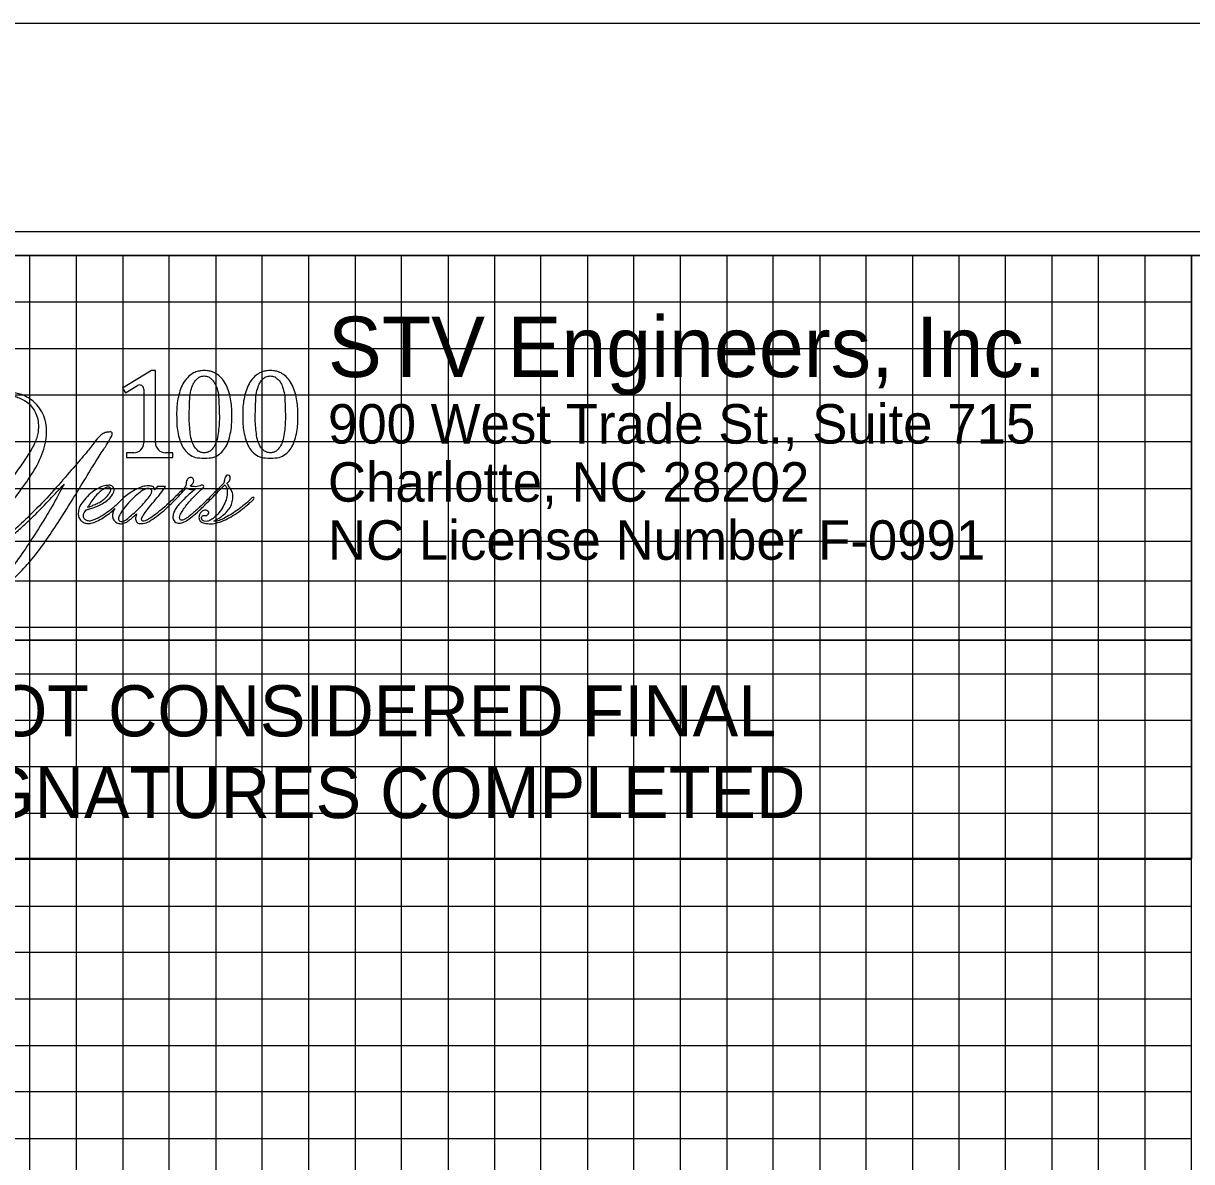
# Model space of a CAD drawing. Extents: x 3814791 to 3815465, y 1224203 to 1224643.
# Drawn here: x 3815327.8 to 3815378.1, y 1224594.2 to 1224643.2 of the extents above; entities that cross this region are included whole.
import ezdxf

# ---------------------------------------------------------------- set-up
doc = ezdxf.new("R2010")
doc.units = 0
for name, color, linetype in [('COGO Default Curve', 7, 'Continuous'), ('Exist Roads EOP', 7, 'Continuous'), ('Pattern 49', 7, 'Continuous'), ('Scratch_Level_1', 7, 'Continuous'), ('Sheet Layout Plan Border', 7, 'Continuous'), ('UC Full Profile Sheet 34 CELL', 7, 'Continuous')]:
    doc.layers.add(name, color=color, linetype=linetype)

msp = doc.modelspace()

# ---------------------------------------------------------------- linework, layer by layer
at = {"layer": 'COGO Default Curve'}
for p, q in [((3815298.107, 1224616.652), (3815378.107, 1224616.652)), ((3815378.107, 1224616.652), (3815378.107, 1224607.252)), ((3815378.107, 1224607.252), (3815298.107, 1224607.252))]:
    msp.add_line(p, q, dxfattribs=at)
at = {"layer": 'Exist Roads EOP'}
for p, q in [((3814878.107, 1224633.207), (3815378.107, 1224633.207)), ((3815378.107, 1224623.187), (3815378.132, 1224633.207))]:
    msp.add_line(p, q, dxfattribs=at)
for points in [[(3815458.107, 1224633.207), (3814858.107, 1224633.207), (3814858.107, 1224213.207), (3815458.107, 1224213.207)], [(3814878.107, 1224633.207), (3814878.107, 1224223.207), (3815438.107, 1224223.207), (3815438.107, 1224578.187), (3815378.107, 1224578.187), (3815378.107, 1224633.207)]]:
    msp.add_lwpolyline(points, close=True, dxfattribs=at)
for points in [[(3815328.107, 1224223.207), (3815328.107, 1224633.207), (3815348.107, 1224633.207), (3815348.107, 1224223.207)], [(3815330.107, 1224223.207), (3815330.107, 1224633.207), (3815332.107, 1224633.207), (3815332.107, 1224223.207)], [(3815334.107, 1224223.207), (3815334.107, 1224633.207), (3815336.107, 1224633.207), (3815336.107, 1224223.207)], [(3815338.107, 1224223.207), (3815338.107, 1224633.207), (3815358.107, 1224633.207), (3815358.107, 1224223.207)], [(3815340.107, 1224223.207), (3815340.107, 1224633.207), (3815342.107, 1224633.207), (3815342.107, 1224223.207)], [(3815344.107, 1224223.207), (3815344.107, 1224633.207), (3815346.107, 1224633.207), (3815346.107, 1224223.207)], [(3815350.107, 1224223.207), (3815350.107, 1224633.207), (3815352.107, 1224633.207), (3815352.107, 1224223.207)], [(3815354.107, 1224223.207), (3815354.107, 1224633.207), (3815356.107, 1224633.207), (3815356.107, 1224223.207)], [(3815360.107, 1224223.207), (3815360.107, 1224633.207), (3815362.107, 1224633.207), (3815362.107, 1224223.207)], [(3815364.107, 1224223.207), (3815364.107, 1224633.207), (3815366.107, 1224633.207), (3815366.107, 1224223.207)], [(3815368.107, 1224223.207), (3815368.107, 1224633.207)], [(3815370.107, 1224223.207), (3815370.107, 1224633.207), (3815372.107, 1224633.207), (3815372.107, 1224223.207)], [(3815374.107, 1224223.207), (3815374.107, 1224633.207), (3815376.107, 1224633.207), (3815376.107, 1224223.207)], [(3815378.107, 1224223.207), (3815378.107, 1224633.207), (3815388.627, 1224633.207)], [(3815418.137, 1224623.252), (3815418.137, 1224578.187), (3815378.107, 1224578.187), (3815378.107, 1224633.207), (3815418.137, 1224633.207), (3815418.137, 1224633.147)], [(3815378.087, 1224631.207), (3814878.107, 1224631.207), (3814878.107, 1224629.207), (3815378.087, 1224629.207)], [(3815378.087, 1224627.207), (3814878.107, 1224627.207), (3814878.107, 1224625.207), (3815378.087, 1224625.207)], [(3815378.087, 1224603.207), (3814858.147, 1224603.207), (3814858.147, 1224623.187), (3815378.087, 1224623.187)], [(3815378.087, 1224620.907), (3814878.107, 1224620.907), (3814878.107, 1224619.207), (3815378.087, 1224619.207)], [(3815378.087, 1224617.207), (3814878.107, 1224617.207), (3814878.107, 1224615.207), (3815378.087, 1224615.207)], [(3814858.107, 1224613.207), (3815378.087, 1224613.207)], [(3815378.087, 1224611.207), (3814878.107, 1224611.207), (3814878.107, 1224609.207), (3815378.087, 1224609.207)], [(3815378.107, 1224607.207), (3814878.107, 1224607.207), (3814878.107, 1224605.207), (3815378.087, 1224605.207)], [(3815378.087, 1224601.207), (3814878.107, 1224601.207), (3814878.107, 1224599.207), (3815378.087, 1224599.207)], [(3815378.087, 1224597.207), (3814878.107, 1224597.207), (3814878.107, 1224595.207), (3815378.087, 1224595.207)]]:
    msp.add_lwpolyline(points, dxfattribs=at)
at = {"layer": 'Pattern 49'}
msp.add_lwpolyline([(3815463.107, 1224634.227), (3814796.507, 1224634.227), (3814796.507, 1224212.187), (3815463.107, 1224212.187)], close=True, dxfattribs=at)
at = {"layer": 'Scratch_Level_1'}
msp.add_lwpolyline([(3815464.907, 1224643.207), (3814791.307, 1224643.207), (3814791.307, 1224203.207), (3815464.907, 1224203.207)], close=True, dxfattribs=at)
at = {"layer": 'Sheet Layout Plan Border'}
for p, q in [((3815333.337, 1224628.261), (3815332.095, 1224627.499)), ((3815333.51, 1224628.261), (3815333.337, 1224628.261)), ((3815333.51, 1224625.153), (3815333.51, 1224628.261)), ((3815332.222, 1224627.301), (3815332.737, 1224627.617)), ((3815332.095, 1224627.499), (3815332.222, 1224627.301)), ((3815333.008, 1224627.465), (3815333.008, 1224625.153)), ((3815332.581, 1224624.726), (3815332.261, 1224624.726)), ((3815332.261, 1224624.726), (3815332.261, 1224624.517)), ((3815334.258, 1224624.726), (3815333.938, 1224624.726)), ((3815334.258, 1224624.517), (3815334.258, 1224624.726)), ((3815335.613, 1224624.718), (3815335.61, 1224624.718)), ((3815338.456, 1224624.718), (3815338.454, 1224624.718)), ((3815332.261, 1224624.517), (3815334.258, 1224624.517)), ((3815335.611, 1224624.489), (3815335.612, 1224624.489)), ((3815338.455, 1224624.489), (3815338.455, 1224624.489))]:
    msp.add_line(p, q, dxfattribs=at)
msp.add_lwpolyline([(3815298.107, 1224633.207), (3815378.107, 1224633.207), (3815378.107, 1224616.652), (3815298.107, 1224616.652)], close=True, dxfattribs=at)
for centre, radius, start, end in [((3815332.83, 1224627.465), 0.178, 360, 121.5268), ((3815332.581, 1224625.153), 0.428, 270, 0), ((3815333.938, 1224625.153), 0.428, 180, 270)]:
    msp.add_arc(centre, radius, start, end, dxfattribs=at)
for points, degree in [([(3815335.611, 1224628.261), (3815335.58, 1224628.26), (3815335.478, 1224628.257), (3815335.31, 1224628.228), (3815335.097, 1224628.14), (3815334.88, 1224627.971), (3815334.681, 1224627.703), (3815334.561, 1224627.388), (3815334.47, 1224627.04), (3815334.43, 1224626.713), (3815334.423, 1224626.482), (3815334.421, 1224626.389)], 3), ([(3815336.802, 1224626.389), (3815336.799, 1224626.482), (3815336.793, 1224626.713), (3815336.753, 1224627.04), (3815336.662, 1224627.388), (3815336.541, 1224627.703), (3815336.342, 1224627.971), (3815336.126, 1224628.14), (3815335.913, 1224628.228), (3815335.745, 1224628.257), (3815335.643, 1224628.26), (3815335.611, 1224628.261)], 3), ([(3815338.455, 1224628.261), (3815338.424, 1224628.26), (3815338.321, 1224628.257), (3815338.154, 1224628.228), (3815337.94, 1224628.14), (3815337.724, 1224627.971), (3815337.525, 1224627.703), (3815337.405, 1224627.388), (3815337.314, 1224627.04), (3815337.274, 1224626.713), (3815337.267, 1224626.482), (3815337.265, 1224626.389)], 3), ([(3815339.646, 1224626.389), (3815339.643, 1224626.482), (3815339.636, 1224626.713), (3815339.597, 1224627.04), (3815339.505, 1224627.388), (3815339.385, 1224627.703), (3815339.186, 1224627.971), (3815338.97, 1224628.14), (3815338.756, 1224628.228), (3815338.589, 1224628.257), (3815338.486, 1224628.26), (3815338.455, 1224628.261)], 3), ([(3815334.964, 1224626.389), (3815334.968, 1224626.538), (3815334.977, 1224626.832), (3815334.991, 1224627.239), (3815335.078, 1224627.566), (3815335.193, 1224627.785), (3815335.31, 1224627.917), (3815335.425, 1224627.992), (3815335.513, 1224628.02), (3815335.575, 1224628.024), (3815335.611, 1224628.027)], 3), ([(3815335.611, 1224628.027), (3815335.648, 1224628.024), (3815335.71, 1224628.02), (3815335.798, 1224627.992), (3815335.913, 1224627.917), (3815336.03, 1224627.785), (3815336.145, 1224627.566), (3815336.232, 1224627.239), (3815336.246, 1224626.832), (3815336.254, 1224626.538), (3815336.259, 1224626.389)], 3), ([(3815337.808, 1224626.389), (3815337.812, 1224626.538), (3815337.821, 1224626.832), (3815337.835, 1224627.239), (3815337.922, 1224627.566), (3815338.036, 1224627.785), (3815338.153, 1224627.917), (3815338.269, 1224627.992), (3815338.357, 1224628.02), (3815338.419, 1224628.024), (3815338.455, 1224628.027)], 3), ([(3815338.455, 1224628.027), (3815338.491, 1224628.024), (3815338.553, 1224628.02), (3815338.641, 1224627.992), (3815338.757, 1224627.917), (3815338.874, 1224627.785), (3815338.989, 1224627.566), (3815339.075, 1224627.239), (3815339.09, 1224626.832), (3815339.098, 1224626.538), (3815339.102, 1224626.389)], 3), ([(3815329.579, 1224623.37), (3815329.48, 1224623.182), (3815329.145, 1224622.541), (3815328.559, 1224621.583), (3815327.905, 1224620.564), (3815327.301, 1224619.72), (3815326.755, 1224619.129), (3815326.278, 1224618.692), (3815325.912, 1224618.471), (3815325.578, 1224618.312), (3815325.273, 1224618.284), (3815325.005, 1224618.326), (3815324.819, 1224618.475), (3815324.729, 1224618.652), (3815324.739, 1224618.8), (3815324.823, 1224618.892), (3815324.952, 1224618.897), (3815325.113, 1224618.904), (3815325.316, 1224618.974), (3815325.376, 1224619.217), (3815325.208, 1224619.41), (3815324.944, 1224619.393), (3815324.741, 1224619.217), (3815324.57, 1224618.983), (3815324.588, 1224618.694), (3815324.672, 1224618.439), (3815324.863, 1224618.251), (3815325.148, 1224618.157), (3815325.447, 1224618.169), (3815325.782, 1224618.232), (3815326.176, 1224618.393), (3815326.609, 1224618.663), (3815327.118, 1224619.03), (3815327.702, 1224619.583), (3815328.276, 1224620.224), (3815328.842, 1224620.996), (3815329.371, 1224621.797), (3815330.015, 1224622.822), (3815330.587, 1224623.772), (3815331.072, 1224624.563), (3815331.375, 1224625.002), (3815331.546, 1224625.309), (3815331.648, 1224625.457), (3815331.669, 1224625.635), (3815331.494, 1224625.613), (3815331.348, 1224625.603), (3815331.179, 1224625.505), (3815330.995, 1224625.331), (3815330.752, 1224624.985), (3815330.309, 1224624.456), (3815329.642, 1224623.687), (3815328.836, 1224622.757), (3815327.977, 1224621.898), (3815327.33, 1224621.296), (3815326.897, 1224621.026), (3815326.704, 1224620.914), (3815326.492, 1224620.904), (3815326.428, 1224621.1), (3815326.477, 1224621.314), (3815326.661, 1224621.749), (3815326.984, 1224622.165), (3815327.421, 1224622.729), (3815327.888, 1224623.348), (3815328.443, 1224624.171), (3815328.82, 1224625.107), (3815328.854, 1224626.058), (3815328.487, 1224626.765), (3815327.968, 1224627.164), (3815327.513, 1224627.304), (3815327.23, 1224627.348), (3815327.124, 1224627.359)], 3), ([(3815327.277, 1224627.183), (3815327.281, 1224627.182), (3815327.347, 1224627.169), (3815327.47, 1224627.146), (3815327.702, 1224627.074), (3815327.938, 1224626.939), (3815328.175, 1224626.739), (3815328.324, 1224626.502), (3815328.443, 1224626.242), (3815328.481, 1224625.926), (3815328.461, 1224625.507), (3815328.279, 1224625.035), (3815327.959, 1224624.515), (3815327.58, 1224623.964), (3815327.008, 1224623.21), (3815326.426, 1224622.443), (3815326.116, 1224621.654), (3815326.097, 1224621.181), (3815326.2, 1224620.905), (3815326.385, 1224620.765), (3815326.559, 1224620.758), (3815326.796, 1224620.797), (3815327.062, 1224620.953), (3815327.382, 1224621.175), (3815327.809, 1224621.568), (3815328.345, 1224622.056), (3815328.964, 1224622.718), (3815329.362, 1224623.14), (3815329.579, 1224623.37)], 3), ([(3815334.421, 1224626.389), (3815334.423, 1224626.313), (3815334.43, 1224626.114), (3815334.434, 1224625.794), (3815334.504, 1224625.445), (3815334.6, 1224625.113), (3815334.756, 1224624.846), (3815334.947, 1224624.65), (3815335.225, 1224624.499), (3815335.458, 1224624.493), (3815335.611, 1224624.489)], 3), ([(3815335.61, 1224624.718), (3815335.559, 1224624.722), (3815335.437, 1224624.732), (3815335.272, 1224624.854), (3815335.128, 1224625.072), (3815335.027, 1224625.369), (3815334.993, 1224625.723), (3815334.958, 1224626.064), (3815334.962, 1224626.287), (3815334.964, 1224626.389)], 3), ([(3815335.612, 1224624.489), (3815335.765, 1224624.493), (3815335.998, 1224624.499), (3815336.276, 1224624.65), (3815336.467, 1224624.846), (3815336.622, 1224625.113), (3815336.718, 1224625.445), (3815336.789, 1224625.794), (3815336.793, 1224626.114), (3815336.799, 1224626.313), (3815336.802, 1224626.389)], 3), ([(3815336.259, 1224626.389), (3815336.261, 1224626.287), (3815336.265, 1224626.064), (3815336.23, 1224625.723), (3815336.196, 1224625.369), (3815336.094, 1224625.072), (3815335.951, 1224624.854), (3815335.786, 1224624.732), (3815335.664, 1224624.722), (3815335.613, 1224624.718)], 3), ([(3815337.265, 1224626.389), (3815337.267, 1224626.313), (3815337.274, 1224626.114), (3815337.277, 1224625.794), (3815337.348, 1224625.445), (3815337.444, 1224625.113), (3815337.6, 1224624.846), (3815337.791, 1224624.65), (3815338.069, 1224624.499), (3815338.301, 1224624.493), (3815338.455, 1224624.489)], 3), ([(3815338.454, 1224624.718), (3815338.403, 1224624.722), (3815338.281, 1224624.732), (3815338.115, 1224624.854), (3815337.972, 1224625.072), (3815337.87, 1224625.369), (3815337.837, 1224625.723), (3815337.802, 1224626.064), (3815337.806, 1224626.287), (3815337.808, 1224626.389)], 3), ([(3815338.455, 1224624.489), (3815338.609, 1224624.493), (3815338.842, 1224624.499), (3815339.119, 1224624.65), (3815339.31, 1224624.846), (3815339.466, 1224625.113), (3815339.562, 1224625.445), (3815339.633, 1224625.794), (3815339.636, 1224626.114), (3815339.643, 1224626.313), (3815339.646, 1224626.389)], 3), ([(3815339.102, 1224626.389), (3815339.104, 1224626.287), (3815339.108, 1224626.064), (3815339.074, 1224625.723), (3815339.04, 1224625.369), (3815338.938, 1224625.072), (3815338.795, 1224624.854), (3815338.629, 1224624.732), (3815338.508, 1224624.722), (3815338.456, 1224624.718)], 3), ([(3815336.019, 1224621.775), (3815336.06, 1224621.797), (3815336.194, 1224621.867), (3815336.403, 1224622.012), (3815336.61, 1224622.199), (3815336.765, 1224622.425), (3815336.845, 1224622.676), (3815336.854, 1224622.946), (3815336.771, 1224623.146), (3815336.671, 1224623.263), (3815336.635, 1224623.342), (3815336.592, 1224623.387), (3815336.608, 1224623.448), (3815336.675, 1224623.472), (3815336.718, 1224623.556), (3815336.742, 1224623.646), (3815336.707, 1224623.76), (3815336.587, 1224623.77), (3815336.516, 1224623.686), (3815336.464, 1224623.581), (3815336.491, 1224623.428), (3815336.326, 1224623.304), (3815336.156, 1224623.103), (3815335.85, 1224622.807), (3815335.545, 1224622.496), (3815335.265, 1224622.259), (3815335.104, 1224622.103), (3815334.969, 1224621.986), (3815334.827, 1224621.894), (3815334.717, 1224621.823), (3815334.576, 1224621.801), (3815334.538, 1224621.936), (3815334.57, 1224622.041), (3815334.653, 1224622.193), (3815334.776, 1224622.379), (3815334.944, 1224622.599), (3815335.114, 1224622.78), (3815335.287, 1224622.949), (3815335.431, 1224623.106), (3815335.557, 1224623.191), (3815335.612, 1224623.271), (3815335.543, 1224623.356), (3815335.429, 1224623.3), (3815335.306, 1224623.256), (3815335.194, 1224623.267), (3815334.981, 1224623.267), (3815335.043, 1224623.326), (3815335.081, 1224623.367), (3815335.168, 1224623.438), (3815335.167, 1224623.582), (3815335.069, 1224623.677), (3815334.948, 1224623.654), (3815334.869, 1224623.563), (3815334.822, 1224623.454), (3815334.84, 1224623.365), (3815334.79, 1224623.235), (3815334.627, 1224623.094), (3815334.384, 1224622.842), (3815334.095, 1224622.556), (3815333.733, 1224622.245), (3815333.432, 1224622), (3815333.187, 1224621.848), (3815333.062, 1224621.782), (3815332.967, 1224621.774), (3815332.91, 1224621.814), (3815332.906, 1224621.884), (3815332.941, 1224621.953), (3815333.026, 1224622.096), (3815333.175, 1224622.304), (3815333.454, 1224622.631), (3815333.715, 1224622.953), (3815333.894, 1224623.192), (3815333.949, 1224623.266)], 3), ([(3815333.471, 1224623.121), (3815333.462, 1224623.211), (3815333.416, 1224623.286), (3815333.222, 1224623.302), (3815332.959, 1224623.285), (3815332.68, 1224623.157), (3815332.445, 1224623.018), (3815332.199, 1224622.849), (3815331.979, 1224622.631), (3815331.756, 1224622.4), (3815331.433, 1224622.156), (3815331.315, 1224622.078), (3815331.115, 1224621.94), (3815330.901, 1224621.853), (3815330.721, 1224621.773), (3815330.575, 1224621.785), (3815330.472, 1224621.839), (3815330.405, 1224621.944), (3815330.406, 1224622.082), (3815330.469, 1224622.178), (3815330.511, 1224622.273), (3815330.641, 1224622.29), (3815330.819, 1224622.35), (3815331.038, 1224622.423), (3815331.266, 1224622.564), (3815331.503, 1224622.714), (3815331.684, 1224622.926), (3815331.765, 1224623.171), (3815331.633, 1224623.326), (3815331.478, 1224623.322), (3815331.273, 1224623.305), (3815331.014, 1224623.178), (3815330.707, 1224622.985), (3815330.449, 1224622.69), (3815330.232, 1224622.425), (3815330.179, 1224622.159), (3815330.193, 1224621.979), (3815330.269, 1224621.815), (3815330.4, 1224621.722), (3815330.552, 1224621.666), (3815330.735, 1224621.672), (3815330.989, 1224621.761), (3815331.254, 1224621.924), (3815331.535, 1224622.108), (3815331.685, 1224622.249), (3815331.757, 1224622.317)], 3), ([(3815330.585, 1224622.374), (3815330.635, 1224622.45), (3815330.728, 1224622.589), (3815330.903, 1224622.828), (3815331.081, 1224623.025), (3815331.277, 1224623.157), (3815331.387, 1224623.234), (3815331.488, 1224623.253), (3815331.561, 1224623.229), (3815331.607, 1224623.146), (3815331.553, 1224623.011), (3815331.452, 1224622.87), (3815331.293, 1224622.715), (3815331.099, 1224622.577), (3815330.905, 1224622.498), (3815330.734, 1224622.423), (3815330.642, 1224622.393), (3815330.585, 1224622.374)], 3), ([(3815332.66, 1224622.188), (3815332.586, 1224622.125), (3815332.415, 1224621.98), (3815332.216, 1224621.801), (3815332.024, 1224621.747), (3815331.916, 1224621.799), (3815331.92, 1224621.947), (3815332.013, 1224622.158), (3815332.279, 1224622.491), (3815332.578, 1224622.804), (3815332.849, 1224623.04), (3815333.009, 1224623.139), (3815333.144, 1224623.182), (3815333.269, 1224623.196), (3815333.406, 1224623.068), (3815333.238, 1224622.821), (3815333.052, 1224622.594), (3815332.842, 1224622.367), (3815332.708, 1224622.235), (3815332.66, 1224622.188)], 3), ([(3815332.691, 1224622.087), (3815332.681, 1224622.051), (3815332.657, 1224621.964), (3815332.645, 1224621.822), (3815332.737, 1224621.675), (3815332.915, 1224621.667), (3815333.167, 1224621.7), (3815333.461, 1224621.922), (3815333.803, 1224622.16), (3815334.074, 1224622.427), (3815334.324, 1224622.658), (3815334.571, 1224622.916), (3815334.749, 1224623.108), (3815334.848, 1224623.215)], 3), ([(3815333.594, 1224623.266), (3815333.553, 1224623.217), (3815333.512, 1224623.169), (3815333.471, 1224623.121)], 2), ([(3815333.949, 1224623.266), (3815333.831, 1224623.266), (3815333.712, 1224623.266), (3815333.594, 1224623.266)], 2), ([(3815335.217, 1224623.141), (3815335.128, 1224623.075), (3815334.947, 1224622.94), (3815334.738, 1224622.72), (3815334.549, 1224622.526), (3815334.41, 1224622.365), (3815334.314, 1224622.196), (3815334.258, 1224622.024), (3815334.258, 1224621.823), (3815334.43, 1224621.678), (3815334.638, 1224621.699), (3815334.843, 1224621.78), (3815335.074, 1224621.963), (3815335.378, 1224622.208), (3815335.855, 1224622.693), (3815336.23, 1224623.074), (3815336.49, 1224623.339)], 3), ([(3815334.848, 1224623.215), (3815334.883, 1224623.195), (3815334.96, 1224623.15), (3815335.091, 1224623.139), (3815335.179, 1224623.14), (3815335.217, 1224623.141)], 3), ([(3815336.49, 1224623.339), (3815336.515, 1224623.313), (3815336.589, 1224623.236), (3815336.602, 1224623.025), (3815336.595, 1224622.777), (3815336.466, 1224622.486), (3815336.298, 1224622.192), (3815336.08, 1224621.959), (3815335.894, 1224621.821), (3815335.741, 1224621.76), (3815335.605, 1224621.765), (3815335.519, 1224621.825), (3815335.476, 1224621.9), (3815335.505, 1224621.977), (3815335.561, 1224622.028), (3815335.635, 1224622.021), (3815335.719, 1224622.007), (3815335.793, 1224622.075), (3815335.826, 1224622.172), (3815335.723, 1224622.253), (3815335.579, 1224622.262), (3815335.451, 1224622.156), (3815335.384, 1224622.019), (3815335.374, 1224621.852), (3815335.498, 1224621.708), (3815335.74, 1224621.666), (3815336.033, 1224621.658), (3815336.353, 1224621.762), (3815336.686, 1224621.906), (3815337.005, 1224622.121), (3815337.357, 1224622.367), (3815337.59, 1224622.59), (3815337.754, 1224622.721), (3815337.766, 1224622.817), (3815337.689, 1224622.807), (3815337.602, 1224622.72), (3815337.461, 1224622.582), (3815337.211, 1224622.385), (3815336.951, 1224622.182), (3815336.663, 1224622.006), (3815336.412, 1224621.881), (3815336.201, 1224621.776), (3815336.067, 1224621.775), (3815336.019, 1224621.775)], 3), ([(3815331.757, 1224622.317), (3815331.731, 1224622.268), (3815331.687, 1224622.181), (3815331.656, 1224622.025), (3815331.678, 1224621.855), (3815331.8, 1224621.719), (3815331.968, 1224621.659), (3815332.141, 1224621.672), (3815332.308, 1224621.762), (3815332.446, 1224621.868), (3815332.574, 1224621.983), (3815332.651, 1224622.052), (3815332.691, 1224622.087)], 3)]:
    msp.add_open_spline(points, degree=degree, dxfattribs=at)
at = {"layer": 'UC Full Profile Sheet 34 CELL'}
msp.add_lwpolyline([(3815298.107, 1224633.207), (3815378.107, 1224633.207), (3815378.107, 1224607.252), (3815333.021, 1224607.252), (3815318.649, 1224607.252), (3815298.107, 1224607.252)], close=True, dxfattribs=at)

# ---------------------------------------------------------------- texts
at = {"layer": 'COGO Default Curve'}
for s, p in [('DOCUMENT NOT CONSIDERED FINAL', (3815306.627, 1224612.514)), ('UNLESS ALL SIGNATURES COMPLETED', (3815304.599, 1224608.994))]:
    msp.add_text(s, height=2.2, rotation=360, dxfattribs=at).set_placement(p)
at = {"layer": 'Sheet Layout Plan Border'}
for s, height, p in [('STV Engineers, Inc.', 2.6, (3815340.936, 1224627.982)), ('900 West Trade St., Suite 715', 1.7, (3815340.936, 1224625.116)), ('Charlotte, NC 28202', 1.7, (3815340.936, 1224622.616)), ('NC License Number F-0991', 1.7, (3815340.936, 1224620.116))]:
    msp.add_text(s, height=height, rotation=360, dxfattribs=at).set_placement(p)

doc.saveas('drawing.dxf')
